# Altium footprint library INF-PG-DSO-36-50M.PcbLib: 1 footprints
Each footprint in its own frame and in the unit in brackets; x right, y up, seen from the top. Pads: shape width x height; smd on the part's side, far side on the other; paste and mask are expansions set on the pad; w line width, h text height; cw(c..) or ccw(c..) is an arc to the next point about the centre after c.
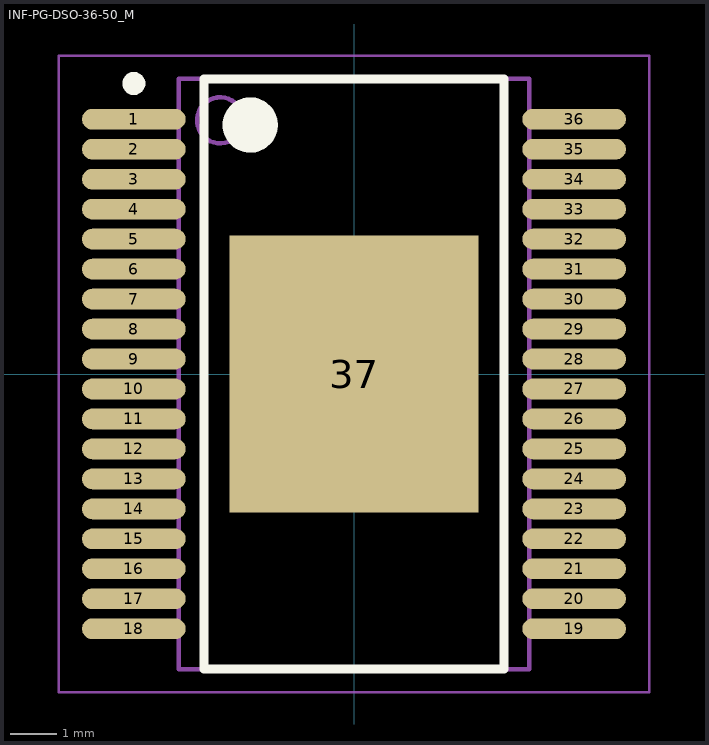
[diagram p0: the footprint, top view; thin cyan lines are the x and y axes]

## INF-PG-DSO-36-50_M [mm] "SOP, 36-Leads, Body 12.7x7.5mm, Pitch 0.65mm, Thermal Pad 6000x5400mm, IPC Low Density"
height 2.55
pads (37):
  oval 2.25x0.45 smd: 1(-4.775,5.525) 2(-4.775,4.875) 3(-4.775,4.225) 4(-4.775,3.575) 5(-4.775,2.925) 6(-4.775,2.275) 7(-4.775,1.625) 8(-4.775,0.975) 9(-4.775,0.325) 10(-4.775,-0.325) 11(-4.775,-0.975) 12(-4.775,-1.625) 13(-4.775,-2.275) 14(-4.775,-2.925) 15(-4.775,-3.575) 16(-4.775,-4.225) 17(-4.775,-4.875) 18(-4.775,-5.525) 19(4.775,-5.525) 20(4.775,-4.875) 21(4.775,-4.225) 22(4.775,-3.575) 23(4.775,-2.925) 24(4.775,-2.275) 25(4.775,-1.625) 26(4.775,-0.975) 27(4.775,-0.325) 28(4.775,0.325) 29(4.775,0.975) 30(4.775,1.625) 31(4.775,2.275) 32(4.775,2.925) 33(4.775,3.575) 34(4.775,4.225) 35(4.775,4.875) 36(4.775,5.525)
  rect 5.4x6 smd: 37(0,0)
Top Overlay:
  circle w0.25: c-4.775,6.3 r0.125
  circle w0.6: c-2.25,5.4 r0.3
  lines w0.2: -3.25,-6.4 -3.25,6.4 3.25,6.4 3.25,-6.4 -3.25,-6.4
Mechanical 13:
  circle w0.1: c-2.9,5.5 r0.5
  lines w0.1: -3.8,-6.4 -3.8,6.4 3.8,6.4 3.8,-6.4 -3.8,-6.4
Mechanical 15:
  lines w0.05: -6.4,-6.9 -6.4,6.9 6.4,6.9 6.4,-6.9 -6.4,-6.9
  lines w0.1: -0.5,0 0.5,0 ; 0,-0.5 0,0.5
3D body: height 2.55, standoff 0, extent -3.8,-6.4 3.8,6.4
